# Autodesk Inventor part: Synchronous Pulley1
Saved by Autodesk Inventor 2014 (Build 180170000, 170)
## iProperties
Created: 2013-12
Part Number: Synchronous Pulley1
Material: Steel
Document SubType Name: Modeling
Designer: Bram
Density: 1 g/cm^3
Appearance: Steel
CustomPartVersion: 1
Author: Bram
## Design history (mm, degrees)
sketch "Pulley Sketch"
  geometry: L1 (-0.659, 7.803)-(-0.419, 7.145); L2 (-0.419, 7.145)-(0.419, 7.145); L3 (0.419, 7.145)-(0.659, 7.803); L4 (0, 0)-(0, 7.831); C1 r 8.085 at (0, 0); A1 r 7.831 centre (0, 0) between (-0.659, 7.803) and (0.659, 7.803); 2 further points
  constraints: 8 end point, 3 coincident, 3 point on circle, 2 centre point, 1 horizontal, 1 midpoint, 1 point on line, 1 vertical, 1 vertical alignment, 3 other
  dimensions: "d0" = 16.17014 diameter of C1 (computed from da_pb, da_z); "d1" = 0.254 radial gap between concentric circles of C1 A1 (= da_a); "d2" = 0.6858 dimension on A1 (= da_hg); "d3" = 40 deg angle of L3 L1 (= 2 x da_fi); "d4" = 0.8382 distance of L1.end L2.end (= da_bw)
extrude "Base Body" new body sketch "Pulley Sketch" stored distance "d5" = 8.89 (= da_bf); taper "d6" = 0 deg
extrude "Tooth" cut sketch "Pulley Sketch" stored distance "d7" = 8.89 (= da_bf); taper "d8" = 0 deg
fillet "Tooth Fillet" dims "d9" = 0.254 (= da_rb), "d10" = 0.127 (= da_rt)
feature "Left flange"
feature "Right flange"
body "Solid1"
pattern_circular "Teeth" dims angle "d12" = 360 deg
other parameters: "da_pb" = 2.032 [user parameter; used in 1 equation term], "da_fi" = 20 deg [user parameter; used in 1 equation term], "da_hg" = 0.6858 [user parameter; used in 1 equation term], "da_bw" = 0.8382 [user parameter; used in 1 equation term], "da_rb" = 0.254 [user parameter; used in 1 equation term], "da_rt" = 0.127 [user parameter; used in 1 equation term], "da_a" = 0.254 [user parameter; used in 3 equation terms], "da_bf" = 8.89 [user parameter; used in 2 equation terms], "d15" = 0, "da_wf" = 1.27 [user parameter; used in 2 equation terms], "da_hf" = 1.27 [user parameter; used in 2 equation terms], "d16" = 0
